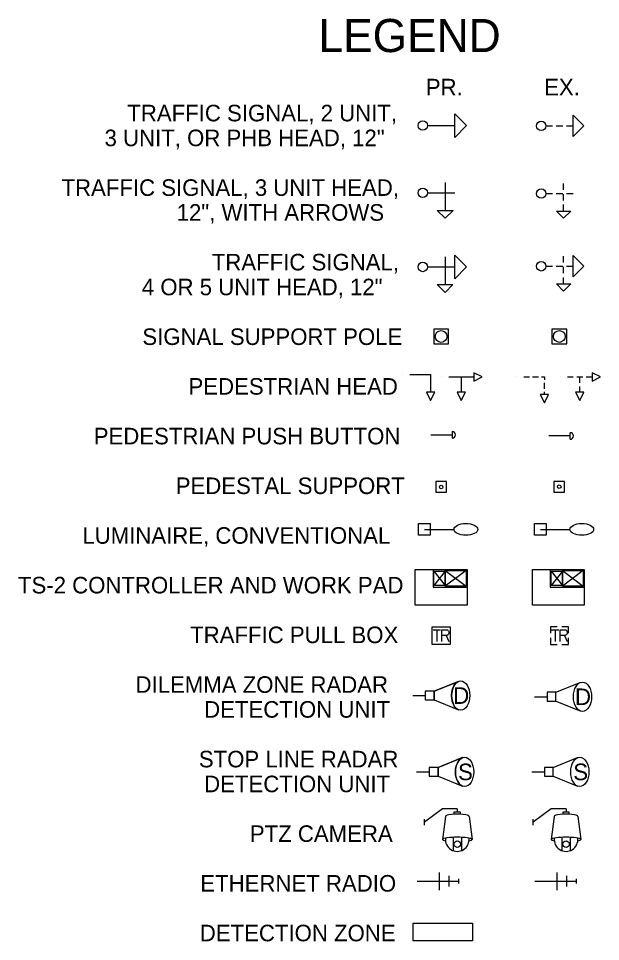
# Model space of a CAD drawing. Extents: x -30.3 to 21.6, y 6.6 to 27.2.
# Drawn here: x 5.18 to 10.1, y 6.91 to 14.71 of the extents above; entities that cross this region are included whole.
import ezdxf

# ---------------------------------------------------------------- set-up
doc = ezdxf.new("R2010")
doc.units = 0
for name, color, linetype in [('DR_X_Elev_Flow', 7, 'Continuous'), ('GE_X_Cells', 7, 'Continuous'), ('GK_Drainage_Nodes', 7, 'Continuous'), ('LT_X_Poles', 7, 'Continuous'), ('RD_X_Bumper_Block', 7, 'Continuous'), ('RD_X_Concrete_Pad', 7, 'Continuous'), ('RD_X_Misc_Items', 7, 'Continuous'), ('RD_X_RR_Cells', 7, 'Continuous'), ('SG_X_Poles', 7, 'Continuous'), ('SG_X_PullBox', 7, 'Continuous'), ('SV_X_Control_Cells_Found', 7, 'Continuous'), ('SV_X_Mon_Cells_Found', 7, 'Continuous'), ('UT_X_Electric_Cells', 7, 'Continuous'), ('UT_X_Gas', 7, 'Continuous'), ('UT_X_Sanitary_Cells', 7, 'Continuous'), ('UT_X_Unknown_Cells', 7, 'Continuous'), ('UT_X_Water', 7, 'Continuous'), ('VG_X_Cells', 7, 'Continuous')]:
    doc.layers.add(name, color=color, linetype=linetype)

msp = doc.modelspace()

# ---------------------------------------------------------------- linework, layer by layer
at = {"layer": 'DR_X_Elev_Flow'}
for p, q in [((9.6391, 13.8018), (9.6941, 13.8018)), ((9.7266, 13.8018), (9.7816, 13.8018)), ((9.8141, 13.8018), (9.8691, 13.8018)), ((9.7884, 13.2612), (9.7884, 13.3162)), ((9.6391, 13.2303), (9.6941, 13.2303)), ((9.7266, 13.2303), (9.7816, 13.2303)), ((9.7884, 13.1712), (9.7884, 13.2262)), ((9.8141, 13.2303), (9.8691, 13.2303)), ((9.7884, 13.0812), (9.7884, 13.1362)), ((9.7884, 12.646), (9.7884, 12.701)), ((9.6391, 12.6152), (9.6941, 12.6152)), ((9.7266, 12.6152), (9.7816, 12.6152)), ((9.7884, 12.556), (9.7884, 12.611)), ((9.8141, 12.6152), (9.8691, 12.6152)), ((9.7884, 12.466), (9.7884, 12.521)), ((9.3917, 11.6803), (9.3917, 11.6803)), ((9.4517, 11.6803), (9.5017, 11.6803)), ((9.5267, 11.6803), (9.5767, 11.6803)), ((9.6267, 11.5803), (9.6267, 11.6303)), ((9.7602, 11.6803), (9.7602, 11.6803)), ((9.8202, 11.6803), (9.8702, 11.6803)), ((9.9002, 11.6803), (9.9502, 11.6803)), ((9.9252, 11.6303), (9.9252, 11.6803)), ((9.9802, 11.6803), (10.0302, 11.6803)), ((9.6267, 11.5303), (9.6267, 11.5553)), ((9.9252, 11.5503), (9.9252, 11.6003))]:
    msp.add_line(p, q, dxfattribs=at)
for points in [[(9.8691, 13.8918), (9.9591, 13.8018), (9.8691, 13.7118)], [(9.8485, 13.0812), (9.7885, 13.0212), (9.7285, 13.0812)], [(9.8691, 12.7052), (9.9591, 12.6152), (9.8691, 12.5252)], [(9.8485, 12.466), (9.7885, 12.406), (9.7285, 12.466)], [(10.0302, 11.7153), (10.0302, 11.6453), (10.1002, 11.6803)], [(9.9602, 11.5503), (9.8902, 11.5503), (9.9252, 11.4803)], [(9.6617, 11.5303), (9.5917, 11.5303), (9.6267, 11.4603)]]:
    msp.add_lwpolyline(points, close=True, dxfattribs=at)
msp.add_lwpolyline([(9.6017, 11.6803), (9.6267, 11.6803), (9.6267, 11.6553)], dxfattribs=at)
for centre in [(9.5991, 13.8018), (9.5991, 13.2303), (9.5991, 12.6152)]:
    msp.add_circle(centre, 0.04, dxfattribs=at)
at = {"layer": 'GE_X_Cells'}
for p, q in [((9.6838, 10.0375), (9.7796, 9.9167)), ((9.7796, 10.0375), (9.6838, 9.9167)), ((9.7796, 10.0438), (9.9546, 9.9105)), ((9.9546, 10.0438), (9.7796, 9.9105))]:
    msp.add_line(p, q, dxfattribs=at)
for points in [[(9.963, 10.0521), (9.963, 9.9021), (9.963, 9.7521), (9.5255, 9.7521), (9.5255, 10.0521), (9.6755, 10.0521)], [(9.6838, 9.9167), (9.6838, 10.0375), (9.7796, 10.0375), (9.7796, 9.9167)], [(9.9546, 9.9105), (9.7796, 9.9105), (9.7796, 10.0438), (9.9546, 10.0438)]]:
    msp.add_lwpolyline(points, close=True, dxfattribs=at)
msp.add_lwpolyline([(9.6755, 10.0521), (9.6755, 9.9021), (9.963, 9.9021)], dxfattribs=at)
at = {"layer": 'GK_Drainage_Nodes'}
msp.add_lwpolyline([(9.7066, 10.7074), (9.7966, 10.7074), (9.7966, 10.7974), (9.7066, 10.7974)], close=True, dxfattribs=at)
msp.add_circle((9.7516, 10.7524), 0.015, dxfattribs=at)
at = {"layer": 'LT_X_Poles'}
msp.add_line((9.7536, 9.4941), (9.7536, 9.4941), dxfattribs=at)
for points in [[(9.7336, 9.5691), (9.6786, 9.5691), (9.6786, 9.5141)], [(9.6858, 9.5441), (9.748, 9.5441)], [(9.7173, 9.5441), (9.7173, 9.4441)], [(9.7592, 9.4441), (9.7592, 9.5441), (9.797, 9.5441), (9.801, 9.5433), (9.8065, 9.5417), (9.8088, 9.5402), (9.8112, 9.5386), (9.8144, 9.5347), (9.8167, 9.5307), (9.8183, 9.5244), (9.8183, 9.515), (9.8175, 9.5118), (9.8159, 9.5071), (9.8128, 9.5016), (9.8096, 9.4992), (9.8073, 9.4977), (9.8057, 9.4969), (9.8033, 9.4961), (9.7962, 9.4953), (9.7592, 9.4953)], [(9.8286, 9.5141), (9.8286, 9.5691), (9.7736, 9.5691)], [(9.6786, 9.4741), (9.6786, 9.4191), (9.7336, 9.4191)], [(9.7736, 9.4191), (9.8286, 9.4191), (9.8286, 9.4741)], [(9.7962, 9.4953), (9.8183, 9.4441)]]:
    msp.add_lwpolyline(points, dxfattribs=at)
at = {"layer": 'RD_X_Bumper_Block'}
for p, q in [((9.7344, 7.3424), (9.7344, 7.4924)), ((9.5444, 7.4174), (9.8944, 7.4174)), ((9.8144, 7.3724), (9.8144, 7.4624)), ((9.8944, 7.4374), (9.8944, 7.3974))]:
    msp.add_line(p, q, dxfattribs=at)
at = {"layer": 'RD_X_Concrete_Pad'}
for p, q in [((8.7412, 7.3424), (8.7412, 7.4924)), ((8.5512, 7.4174), (8.9012, 7.4174)), ((8.8212, 7.3724), (8.8212, 7.4624)), ((8.9012, 7.4374), (8.9012, 7.3974))]:
    msp.add_line(p, q, dxfattribs=at)
at = {"layer": 'RD_X_Misc_Items'}
msp.add_line((8.7541, 9.4941), (8.7541, 9.4941), dxfattribs=at)
msp.add_lwpolyline([(8.6791, 9.5691), (8.8291, 9.5691), (8.8291, 9.4191), (8.6791, 9.4191)], close=True, dxfattribs=at)
for points in [[(8.6863, 9.5441), (8.7485, 9.5441)], [(8.7178, 9.5441), (8.7178, 9.4441)], [(8.7597, 9.4441), (8.7597, 9.5441), (8.7975, 9.5441), (8.8014, 9.5433), (8.807, 9.5417), (8.8093, 9.5402), (8.8117, 9.5386), (8.8148, 9.5347), (8.8172, 9.5307), (8.8188, 9.5244), (8.8188, 9.515), (8.818, 9.5118), (8.8164, 9.5071), (8.8133, 9.5016), (8.8101, 9.4992), (8.8077, 9.4977), (8.8062, 9.4969), (8.8038, 9.4961), (8.7967, 9.4953), (8.7597, 9.4953)], [(8.7967, 9.4953), (8.8188, 9.4441)]]:
    msp.add_lwpolyline(points, dxfattribs=at)
at = {"layer": 'RD_X_RR_Cells'}
msp.add_line((8.6128, 10.3917), (8.8628, 10.3917), dxfattribs=at)
msp.add_lwpolyline([(8.5628, 10.4417), (8.6628, 10.4417), (8.6628, 10.3417), (8.5628, 10.3417)], close=True, dxfattribs=at)
msp.add_ellipse((8.9628, 10.3917), major_axis=(0.1, 0), ratio=0.5, dxfattribs=at)
at = {"layer": 'SG_X_Poles'}
msp.add_lwpolyline([(8.6916, 11.9596), (8.8166, 11.9596), (8.8166, 12.0846), (8.6916, 12.0846)], close=True, dxfattribs=at)
msp.add_circle((8.7541, 12.0221), 0.05, dxfattribs=at)
at = {"layer": 'SG_X_PullBox'}
for p, q in [((8.6667, 11.1905), (8.8467, 11.1905)), ((8.8467, 11.2185), (8.8467, 11.1625)), ((8.6948, 9.0247), (8.9006, 9.1073)), ((8.9006, 9.1073), (8.6948, 9.0247)), ((8.5137, 8.9872), (8.6198, 8.9872)), ((8.6948, 9.0247), (8.6948, 8.9497)), ((8.6948, 8.9497), (8.6948, 9.0247)), ((8.6948, 8.9497), (8.9005, 8.8668)), ((8.6948, 8.9497), (8.9005, 8.8668)), ((8.7276, 8.3798), (8.9335, 8.4624)), ((8.9335, 8.4624), (8.7276, 8.3798)), ((8.7276, 8.3798), (8.7276, 8.3048)), ((8.5465, 8.3423), (8.6526, 8.3423)), ((8.7276, 8.3048), (8.9333, 8.2219)), ((8.7276, 8.3048), (8.9333, 8.2219)), ((8.7905, 7.9659), (8.7655, 7.7702)), ((8.8905, 8.0303), (8.8905, 8.0053)), ((8.9905, 7.9659), (9.0155, 7.7702)), ((8.6123, 7.8925), (8.6123, 7.9425)), ((8.8555, 7.7894), (8.8555, 7.6765)), ((8.9255, 7.7894), (8.9255, 7.6765))]:
    msp.add_line(p, q, dxfattribs=at)
for points in [[(8.6198, 9.0247), (8.6198, 8.9497), (8.6948, 8.9497), (8.6948, 9.0247)], [(8.6526, 8.3798), (8.6526, 8.3048), (8.7276, 8.3048), (8.7276, 8.3798)], [(8.5188, 7.0635), (9.0188, 7.0635), (9.0188, 6.9135), (8.5188, 6.9135)]]:
    msp.add_lwpolyline(points, close=True, dxfattribs=at)
for points in [[(8.6948, 9.0247), (8.6198, 9.0247), (8.6198, 8.9497), (8.6948, 8.9497)], [(8.6526, 8.3798), (8.6526, 8.3048), (8.7276, 8.3048), (8.7276, 8.3798), (8.6526, 8.3798)], [(8.8905, 8.0303), (8.7655, 8.0303), (8.6123, 7.9175)], [(8.8655, 7.9853), (8.8655, 8.0053), (8.9155, 8.0053), (8.9155, 7.9853)]]:
    msp.add_lwpolyline(points, dxfattribs=at)
msp.add_circle((8.8905, 7.7316), 0.0273, dxfattribs=at)
for centre, radius, start, end in [((8.8467, 11.1905), 0.028, 270.00019, 89.99981), ((8.8905, 7.7702), 0.1, 173.0175, 6.9825)]:
    msp.add_arc(centre, radius, start, end, dxfattribs=at)
for centre in [(8.9192, 8.987), (8.9521, 8.3421)]:
    msp.add_ellipse(centre, major_axis=(-0.0001, -0.1239), ratio=0.621318, dxfattribs=at)
for centre, major_axis, ratio, start_param, end_param in [((8.9192, 8.987), (-0.0001, -0.1239), 0.621318, 3.386213, 6.038231), ((8.9521, 8.3421), (-0.0001, -0.1239), 0.621318, 3.386213, 6.038231), ((8.8905, 7.9659), (0.1, 0), 0.2, 0, 3.141593), ((8.8905, 7.7702), (0.125, 0), 0.16, 5.62986, 10.078104)]:
    msp.add_ellipse(centre, major_axis=major_axis, ratio=ratio, start_param=start_param, end_param=end_param, dxfattribs=at)
at = {"layer": 'SV_X_Control_Cells_Found'}
msp.add_line((9.5923, 10.3917), (9.8423, 10.3917), dxfattribs=at)
msp.add_lwpolyline([(9.5423, 10.4417), (9.6423, 10.4417), (9.6423, 10.3417), (9.5423, 10.3417)], close=True, dxfattribs=at)
msp.add_ellipse((9.9423, 10.3917), major_axis=(0.1, 0), ratio=0.5, dxfattribs=at)
at = {"layer": 'SV_X_Mon_Cells_Found'}
for p, q in [((9.8441, 11.181), (9.6641, 11.181)), ((9.8441, 11.153), (9.8441, 11.209)), ((9.7233, 9.0147), (9.9292, 9.0973)), ((9.5423, 8.9772), (9.6483, 8.9772)), ((9.7233, 8.9397), (9.929, 8.8568)), ((9.7007, 8.3798), (9.9065, 8.4624)), ((9.5196, 8.3423), (9.6257, 8.3423)), ((9.7007, 8.3048), (9.9064, 8.2219)), ((9.7089, 7.9659), (9.6839, 7.7702)), ((9.8089, 8.0303), (9.8089, 8.0053)), ((9.9089, 7.9659), (9.9339, 7.7702)), ((9.5306, 7.8925), (9.5306, 7.9425)), ((9.7739, 7.7894), (9.7739, 7.6765)), ((9.8439, 7.7894), (9.8439, 7.6765))]:
    msp.add_line(p, q, dxfattribs=at)
for points in [[(9.6483, 9.0147), (9.6483, 8.9397), (9.7233, 8.9397), (9.7233, 9.0147)], [(9.6257, 8.3798), (9.6257, 8.3048), (9.7007, 8.3048), (9.7007, 8.3798)]]:
    msp.add_lwpolyline(points, close=True, dxfattribs=at)
for points in [[(9.8089, 8.0303), (9.6839, 8.0303), (9.5306, 7.9175)], [(9.7839, 7.9853), (9.7839, 8.0053), (9.8339, 8.0053), (9.8339, 7.9853)]]:
    msp.add_lwpolyline(points, dxfattribs=at)
msp.add_circle((9.8089, 7.7316), 0.0273, dxfattribs=at)
for centre, radius, start, end in [((9.8441, 11.181), 0.028, 270.00019, 89.99981), ((9.8089, 7.7702), 0.1, 173.0175, 6.9825)]:
    msp.add_arc(centre, radius, start, end, dxfattribs=at)
for centre in [(9.9478, 8.977), (9.9251, 8.3421)]:
    msp.add_ellipse(centre, major_axis=(-0.0001, -0.1239), ratio=0.621318, dxfattribs=at)
for centre, major_axis, ratio, start_param, end_param in [((9.8089, 7.9659), (0.1, 0), 0.2, 0, 3.141593), ((9.8089, 7.7702), (0.125, 0), 0.16, 5.62986, 10.078104)]:
    msp.add_ellipse(centre, major_axis=major_axis, ratio=ratio, start_param=start_param, end_param=end_param, dxfattribs=at)
at = {"layer": 'UT_X_Electric_Cells'}
msp.add_lwpolyline([(9.6899, 11.9596), (9.8149, 11.9596), (9.8149, 12.0846), (9.6899, 12.0846)], close=True, dxfattribs=at)
msp.add_circle((9.7524, 12.0221), 0.05, dxfattribs=at)
at = {"layer": 'UT_X_Sanitary_Cells'}
msp.add_lwpolyline([(8.7091, 10.7055), (8.7991, 10.7055), (8.7991, 10.7955), (8.7091, 10.7955)], close=True, dxfattribs=at)
msp.add_circle((8.7541, 10.7505), 0.015, dxfattribs=at)
at = {"layer": 'UT_X_Unknown_Cells'}
for p, q in [((8.6937, 10.0375), (8.7895, 9.9167)), ((8.7895, 10.0375), (8.6937, 9.9167)), ((8.7895, 10.0438), (8.9645, 9.9105)), ((8.9645, 10.0438), (8.7895, 9.9105))]:
    msp.add_line(p, q, dxfattribs=at)
for points in [[(8.9729, 10.0521), (8.9729, 9.9021), (8.9729, 9.7521), (8.5354, 9.7521), (8.5354, 10.0521), (8.6854, 10.0521)], [(8.6937, 9.9167), (8.6937, 10.0375), (8.7895, 10.0375), (8.7895, 9.9167)], [(8.9645, 9.9105), (8.7895, 9.9105), (8.7895, 10.0438), (8.9645, 10.0438)]]:
    msp.add_lwpolyline(points, close=True, dxfattribs=at)
msp.add_lwpolyline([(8.6854, 10.0521), (8.6854, 9.9021), (8.9729, 9.9021)], dxfattribs=at)
at = {"layer": 'VG_X_Cells'}
for p, q in [((8.6391, 13.8051), (8.8691, 13.8051)), ((8.7884, 13.3227), (8.7884, 13.0877)), ((8.6391, 13.2369), (8.8691, 13.2369)), ((8.7884, 12.6953), (8.7884, 12.4603)), ((8.6391, 12.6095), (8.8691, 12.6095)), ((8.4306, 11.7), (8.4306, 11.7)), ((8.7595, 11.6803), (8.7595, 11.6803)), ((8.8195, 11.6803), (9.0295, 11.6803)), ((8.9245, 11.6803), (8.9245, 11.5503))]:
    msp.add_line(p, q, dxfattribs=at)
for points in [[(8.869, 13.905), (8.969, 13.805), (8.869, 13.705)], [(8.8548, 13.088), (8.7881, 13.0213), (8.7215, 13.088)], [(8.8686, 12.7098), (8.9686, 12.6098), (8.8686, 12.5098)], [(8.854, 12.4606), (8.7873, 12.394), (8.7206, 12.4606)], [(9.0295, 11.7153), (9.0295, 11.6453), (9.0995, 11.6803)], [(8.7006, 11.55), (8.6306, 11.55), (8.6656, 11.48)], [(8.9595, 11.5503), (8.8895, 11.5503), (8.9245, 11.4803)]]:
    msp.add_lwpolyline(points, close=True, dxfattribs=at)
msp.add_lwpolyline([(8.4906, 11.7), (8.6656, 11.7), (8.6656, 11.55)], dxfattribs=at)
for centre in [(8.5991, 13.8051), (8.5991, 13.2369), (8.5991, 12.6095)]:
    msp.add_circle(centre, 0.04, dxfattribs=at)

# ---------------------------------------------------------------- texts
at = {"layer": 'SG_X_PullBox'}
for s, p in [('D', (8.8561, 8.917)), ('S', (8.8971, 8.2721))]:
    msp.add_text(s, height=0.14, dxfattribs=at).set_placement(p)
at = {"layer": 'SV_X_Mon_Cells_Found'}
for s, p in [('D', (9.8847, 8.907)), ('S', (9.8702, 8.2721))]:
    msp.add_text(s, height=0.14, dxfattribs=at).set_placement(p)
at = {"layer": 'UT_X_Gas'}
msp.add_text('EX.', height=0.14, dxfattribs=at).set_placement((9.6242, 14.0596))
at = {"layer": 'UT_X_Water'}
for s, height, p in [('LEGEND', 0.28, (7.7176, 14.4256)), ('PR.', 0.14, (8.6247, 14.0596)), ('TRAFFIC SIGNAL, 2 UNIT,', 0.14, (6.1035, 13.8403)), ('3 UNIT, OR PHB HEAD, 12"', 0.14, (5.9115, 13.6303)), ('TRAFFIC SIGNAL, 3 UNIT HEAD,', 0.14, (5.5477, 13.2103)), ('12", WITH ARROWS', 0.14, (6.5205, 13.0003)), ('TRAFFIC SIGNAL, ', 0.14, (6.8169, 12.5803)), ('4 OR 5 UNIT HEAD, 12"', 0.14, (6.2262, 12.3703)), ('SIGNAL SUPPORT POLE', 0.14, (6.2308, 11.9503)), ('PEDESTRIAN HEAD', 0.14, (6.6203, 11.5303)), ('PEDESTRIAN PUSH BUTTON', 0.14, (5.82, 11.1103)), ('PEDESTAL SUPPORT', 0.14, (6.5125, 10.6903)), ('LUMINAIRE, CONVENTIONAL', 0.14, (5.7241, 10.2703)), ('TS-2 CONTROLLER AND WORK PAD', 0.14, (5.1802, 9.8503)), ('TRAFFIC PULL BOX', 0.14, (6.6341, 9.4303)), ('DILEMMA ZONE RADAR', 0.14, (6.1731, 9.0103)), ('DETECTION UNIT', 0.14, (6.7526, 8.8003)), ('STOP LINE RADAR', 0.14, (6.7078, 8.3803)), ('DETECTION UNIT', 0.14, (6.7526, 8.1703)), ('PTZ CAMERA', 0.14, (7.1385, 7.7503)), ('ETHERNET RADIO', 0.14, (6.7202, 7.3303)), ('DETECTION ZONE', 0.14, (6.7158, 6.9103))]:
    msp.add_text(s, height=height, dxfattribs=at).set_placement(p)

doc.saveas('drawing.dxf')
